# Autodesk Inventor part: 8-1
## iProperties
Author: Administrator
Created: 2001-02
Part Number: 8-1
Document SubType Name: Modeling
Designer: Administrator
Control State: 0
Master: False
Checked Out: False
PropertySet Name: Design Tracking Control
Shininess: 20.0
PropertySet Name: _Private Model Information
Density: 0.0
Volumn: 0.0
Area: 0.0
PropertySet Name: Model Information
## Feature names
1. Extrusion1
2. Fillet1
3. Extrusion2
4. Fillet2
5. Hole1
6. Hole2
7. Hole3
